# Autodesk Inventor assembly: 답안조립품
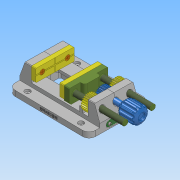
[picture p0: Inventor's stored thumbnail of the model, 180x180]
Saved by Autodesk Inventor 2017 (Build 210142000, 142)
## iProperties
Part Number: 답안조립품
Material: 일반
Document SubType Name: Assembly
Designer: user
Author: user
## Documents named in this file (10)
- C:\Users\user\Desktop\610306V1023\답안조립품.iam
- C:\Users\user\Desktop\610306V1023\바이스본체 A.ipt
- C:\Users\user\Desktop\610306V1023\바이스본체 B.ipt
- C:\Users\user\Desktop\610306V1023\고정 플레이트.ipt
- C:\Users\user\Desktop\610306V1023\십자오목머리나사 M3.ipt
- C:\Users\user\Desktop\610306V1023\십자접시머리나사 M4.ipt
- C:\Users\user\Desktop\610306V1023\지지대.ipt
- C:\Users\user\Desktop\610306V1023\슬라이딩 부품.ipt
- C:\Users\user\Desktop\610306V1023\스퍼기어.ipt
- C:\Users\user\Desktop\610306V1023\핸들.ipt
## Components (3 placed, 2 different names)
1. 고정 플레이트:1
2. 고정 플레이트:2
3. 핸들:1
